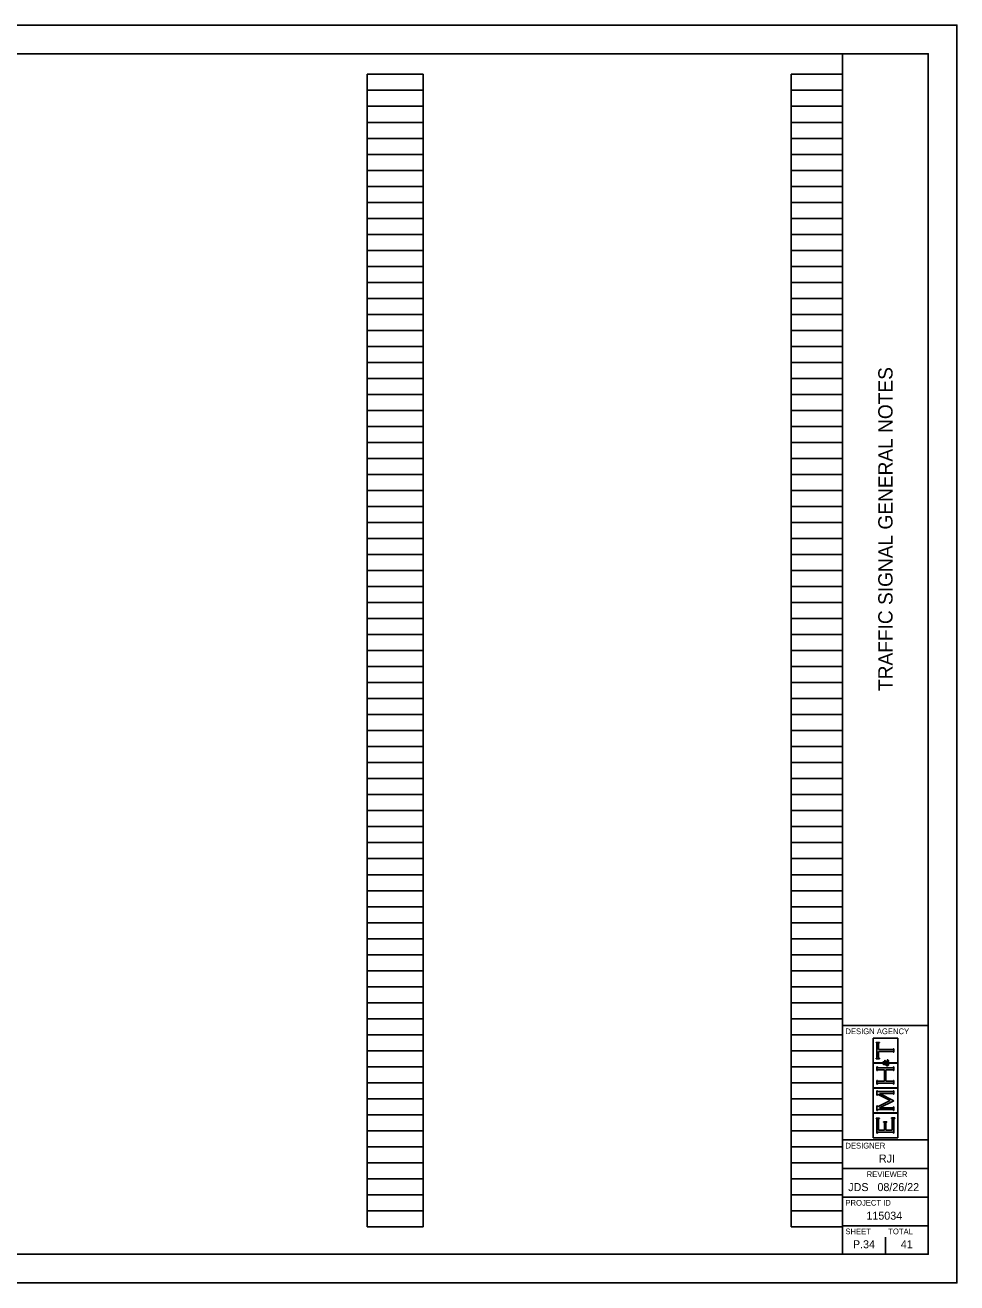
# Model space of a CAD drawing. Extents: x 0 to 34, y 0 to 22.
# Drawn here: x 17.7 to 34, y 0 to 22 of the extents above; entities that cross this region are included whole.
import ezdxf

# ---------------------------------------------------------------- set-up
doc = ezdxf.new("R2010")
doc.units = 0
for name, color, linetype in [('SH_Border', 7, 'Continuous'), ('SH_Cut_Line', 7, 'Continuous'), ('SH_Data', 7, 'Continuous')]:
    doc.layers.add(name, color=color, linetype=linetype)

msp = doc.modelspace()

# ---------------------------------------------------------------- linework, layer by layer
at = {"layer": 'SH_Border'}
for p, q in [((32, 0.5), (32, 21.5)), ((32, 4.5), (33.5, 4.5)), ((32, 2.5), (33.5, 2.5)), ((32, 2), (33.5, 2)), ((32, 1.5), (33.5, 1.5)), ((32, 1), (33.5, 1))]:
    msp.add_line(p, q, dxfattribs=at)
msp.add_lwpolyline([(1.5, 21.5), (33.5, 21.5), (33.5, 0.5), (1.5, 0.5)], close=True, dxfattribs=at)
at = {"layer": 'SH_Cut_Line'}
msp.add_lwpolyline([(0, 0), (34, 0), (34, 22), (0, 22)], close=True, dxfattribs=at)
at = {"layer": 'SH_Data'}
for p, q in [((23.68, 0.98), (23.68, 21.14)), ((23.68, 21.14), (24.66, 21.14)), ((24.66, 0.98), (24.66, 21.14)), ((31.1, 0.98), (31.1, 21.14)), ((31.1, 21.14), (32, 21.14)), ((32, 0.98), (32, 21.14)), ((23.68, 20.86), (24.66, 20.86)), ((31.1, 20.86), (32, 20.86)), ((23.68, 20.58), (24.66, 20.58)), ((31.1, 20.58), (32, 20.58)), ((23.68, 20.3), (24.66, 20.3)), ((31.1, 20.3), (32, 20.3)), ((23.68, 20.02), (24.66, 20.02)), ((31.1, 20.02), (32, 20.02)), ((23.68, 19.74), (24.66, 19.74)), ((31.1, 19.74), (32, 19.74)), ((23.68, 19.46), (24.66, 19.46)), ((31.1, 19.46), (32, 19.46)), ((23.68, 19.18), (24.66, 19.18)), ((31.1, 19.18), (32, 19.18)), ((23.68, 18.9), (24.66, 18.9)), ((31.1, 18.9), (32, 18.9)), ((23.68, 18.62), (24.66, 18.62)), ((31.1, 18.62), (32, 18.62)), ((23.68, 18.34), (24.66, 18.34)), ((31.1, 18.34), (32, 18.34)), ((23.68, 18.06), (24.66, 18.06)), ((31.1, 18.06), (32, 18.06)), ((23.68, 17.78), (24.66, 17.78)), ((31.1, 17.78), (32, 17.78)), ((23.68, 17.5), (24.66, 17.5)), ((31.1, 17.5), (32, 17.5)), ((23.68, 17.22), (24.66, 17.22)), ((31.1, 17.22), (32, 17.22)), ((23.68, 16.94), (24.66, 16.94)), ((31.1, 16.94), (32, 16.94)), ((23.68, 16.66), (24.66, 16.66)), ((31.1, 16.66), (32, 16.66)), ((23.68, 16.38), (24.66, 16.38)), ((31.1, 16.38), (32, 16.38)), ((23.68, 16.1), (24.66, 16.1)), ((31.1, 16.1), (32, 16.1)), ((23.68, 15.82), (24.66, 15.82)), ((31.1, 15.82), (32, 15.82)), ((23.68, 15.54), (24.66, 15.54)), ((31.1, 15.54), (32, 15.54)), ((23.68, 15.26), (24.66, 15.26)), ((31.1, 15.26), (32, 15.26)), ((23.68, 14.98), (24.66, 14.98)), ((31.1, 14.98), (32, 14.98)), ((23.68, 14.7), (24.66, 14.7)), ((31.1, 14.7), (32, 14.7)), ((23.68, 14.42), (24.66, 14.42)), ((31.1, 14.42), (32, 14.42)), ((23.68, 14.14), (24.66, 14.14)), ((31.1, 14.14), (32, 14.14)), ((23.68, 13.86), (24.66, 13.86)), ((31.1, 13.86), (32, 13.86)), ((23.68, 13.58), (24.66, 13.58)), ((31.1, 13.58), (32, 13.58)), ((23.68, 13.3), (24.66, 13.3)), ((31.1, 13.3), (32, 13.3)), ((23.68, 13.02), (24.66, 13.02)), ((31.1, 13.02), (32, 13.02)), ((23.68, 12.74), (24.66, 12.74)), ((31.1, 12.74), (32, 12.74)), ((23.68, 12.46), (24.66, 12.46)), ((31.1, 12.46), (32, 12.46)), ((23.68, 12.18), (24.66, 12.18)), ((31.1, 12.18), (32, 12.18)), ((23.68, 11.9), (24.66, 11.9)), ((31.1, 11.9), (32, 11.9)), ((23.68, 11.62), (24.66, 11.62)), ((31.1, 11.62), (32, 11.62)), ((23.68, 11.34), (24.66, 11.34)), ((31.1, 11.34), (32, 11.34)), ((23.68, 11.06), (24.66, 11.06)), ((31.1, 11.06), (32, 11.06)), ((23.68, 10.78), (24.66, 10.78)), ((31.1, 10.78), (32, 10.78)), ((23.68, 10.5), (24.66, 10.5)), ((31.1, 10.5), (32, 10.5)), ((23.68, 10.22), (24.66, 10.22)), ((31.1, 10.22), (32, 10.22)), ((23.68, 9.94), (24.66, 9.94)), ((31.1, 9.94), (32, 9.94)), ((23.68, 9.66), (24.66, 9.66)), ((31.1, 9.66), (32, 9.66)), ((23.68, 9.38), (24.66, 9.38)), ((31.1, 9.38), (32, 9.38)), ((23.68, 9.1), (24.66, 9.1)), ((31.1, 9.1), (32, 9.1)), ((23.68, 8.82), (24.66, 8.82)), ((31.1, 8.82), (32, 8.82)), ((23.68, 8.54), (24.66, 8.54)), ((31.1, 8.54), (32, 8.54)), ((23.68, 8.26), (24.66, 8.26)), ((31.1, 8.26), (32, 8.26)), ((23.68, 7.98), (24.66, 7.98)), ((31.1, 7.98), (32, 7.98)), ((23.68, 7.7), (24.66, 7.7)), ((31.1, 7.7), (32, 7.7)), ((23.68, 7.42), (24.66, 7.42)), ((31.1, 7.42), (32, 7.42)), ((23.68, 7.14), (24.66, 7.14)), ((31.1, 7.14), (32, 7.14)), ((23.68, 6.86), (24.66, 6.86)), ((31.1, 6.86), (32, 6.86)), ((23.68, 6.58), (24.66, 6.58)), ((31.1, 6.58), (32, 6.58)), ((23.68, 6.3), (24.66, 6.3)), ((31.1, 6.3), (32, 6.3)), ((23.68, 6.02), (24.66, 6.02)), ((31.1, 6.02), (32, 6.02)), ((23.68, 5.74), (24.66, 5.74)), ((31.1, 5.74), (32, 5.74)), ((23.68, 5.46), (24.66, 5.46)), ((31.1, 5.46), (32, 5.46)), ((23.68, 5.18), (24.66, 5.18)), ((31.1, 5.18), (32, 5.18)), ((23.68, 4.9), (24.66, 4.9)), ((31.1, 4.9), (32, 4.9)), ((23.68, 4.62), (24.66, 4.62)), ((31.1, 4.62), (32, 4.62)), ((23.68, 4.34), (24.66, 4.34)), ((31.1, 4.34), (32, 4.34)), ((32.966, 4.28), (32.534, 4.28)), ((32.534, 4.28), (32.534, 3.848)), ((32.588, 4.199), (32.588, 4.206)), ((32.588, 4.206), (32.644, 4.206)), ((32.594, 4.198), (32.588, 4.199)), ((32.598, 4.196), (32.594, 4.198)), ((32.599, 4.194), (32.598, 4.196)), ((32.601, 4.191), (32.599, 4.194)), ((32.602, 4.187), (32.601, 4.191)), ((32.602, 4.181), (32.602, 4.187)), ((32.602, 3.947), (32.602, 4.181)), ((32.632, 4.191), (32.631, 4.187)), ((32.631, 4.187), (32.631, 4.181)), ((32.631, 4.181), (32.631, 4.081)), ((32.633, 4.194), (32.632, 4.191)), ((32.635, 4.196), (32.633, 4.194)), ((32.639, 4.198), (32.635, 4.196)), ((32.644, 4.199), (32.639, 4.198)), ((32.644, 4.206), (32.644, 4.199)), ((32.966, 3.848), (32.966, 4.28)), ((23.68, 4.06), (24.66, 4.06)), ((31.1, 4.06), (32, 4.06)), ((32.631, 4.081), (32.872, 4.081)), ((32.872, 4.047), (32.631, 4.047)), ((32.631, 4.047), (32.631, 3.947)), ((32.872, 4.081), (32.878, 4.081)), ((32.878, 4.047), (32.872, 4.047)), ((32.878, 4.081), (32.882, 4.082)), ((32.883, 4.046), (32.878, 4.047)), ((32.882, 4.082), (32.885, 4.084)), ((32.885, 4.044), (32.883, 4.046)), ((32.885, 4.084), (32.887, 4.085)), ((32.888, 4.042), (32.885, 4.044)), ((32.887, 4.085), (32.889, 4.089)), ((32.889, 4.039), (32.888, 4.042)), ((32.889, 4.089), (32.891, 4.095)), ((32.891, 4.033), (32.889, 4.039)), ((32.891, 4.095), (32.898, 4.095)), ((32.898, 4.033), (32.891, 4.033)), ((32.898, 4.095), (32.898, 4.033)), ((23.68, 3.78), (24.66, 3.78)), ((31.1, 3.78), (32, 3.78)), ((32.534, 3.848), (32.693, 3.848)), ((32.693, 3.842), (32.534, 3.842)), ((32.534, 3.842), (32.534, 3.41)), ((32.588, 3.928), (32.594, 3.93)), ((32.588, 3.921), (32.588, 3.928)), ((32.644, 3.921), (32.588, 3.921)), ((32.594, 3.93), (32.598, 3.932)), ((32.598, 3.932), (32.599, 3.934)), ((32.599, 3.934), (32.601, 3.937)), ((32.601, 3.937), (32.602, 3.941)), ((32.602, 3.941), (32.602, 3.947)), ((32.602, 3.714), (32.602, 3.776)), ((32.602, 3.776), (32.609, 3.776)), ((32.609, 3.776), (32.611, 3.77)), ((32.611, 3.77), (32.612, 3.766)), ((32.612, 3.766), (32.615, 3.765)), ((32.615, 3.765), (32.617, 3.763)), ((32.617, 3.763), (32.622, 3.762)), ((32.622, 3.762), (32.628, 3.762)), ((32.628, 3.762), (32.872, 3.762)), ((32.631, 3.947), (32.631, 3.941)), ((32.631, 3.941), (32.632, 3.937)), ((32.632, 3.937), (32.633, 3.934)), ((32.633, 3.934), (32.635, 3.932)), ((32.635, 3.932), (32.639, 3.93)), ((32.639, 3.93), (32.644, 3.928)), ((32.644, 3.928), (32.644, 3.921)), ((32.693, 3.848), (32.693, 3.842)), ((32.701, 3.852), (32.703, 3.857)), ((32.701, 3.846), (32.701, 3.852)), ((32.701, 3.84), (32.701, 3.846)), ((32.703, 3.835), (32.701, 3.84)), ((32.703, 3.857), (32.706, 3.861)), ((32.706, 3.83), (32.703, 3.835)), ((32.706, 3.861), (32.71, 3.864)), ((32.707, 3.852), (32.706, 3.849)), ((32.706, 3.849), (32.706, 3.846)), ((32.706, 3.846), (32.706, 3.842)), ((32.706, 3.842), (32.708, 3.839)), ((32.71, 3.824), (32.706, 3.83)), ((32.71, 3.854), (32.707, 3.852)), ((32.708, 3.839), (32.711, 3.837)), ((32.71, 3.864), (32.714, 3.866)), ((32.712, 3.856), (32.71, 3.854)), ((32.717, 3.821), (32.71, 3.824)), ((32.711, 3.837), (32.714, 3.835)), ((32.715, 3.857), (32.712, 3.856)), ((32.714, 3.866), (32.719, 3.866)), ((32.714, 3.835), (32.716, 3.834)), ((32.718, 3.857), (32.715, 3.857)), ((32.716, 3.834), (32.719, 3.834)), ((32.725, 3.821), (32.717, 3.821)), ((32.723, 3.857), (32.718, 3.857)), ((32.719, 3.866), (32.724, 3.866)), ((32.719, 3.834), (32.722, 3.834)), ((32.722, 3.834), (32.724, 3.834)), ((32.727, 3.856), (32.723, 3.857)), ((32.724, 3.866), (32.728, 3.864)), ((32.724, 3.834), (32.727, 3.835)), ((32.728, 3.821), (32.725, 3.821)), ((32.73, 3.853), (32.727, 3.856)), ((32.727, 3.835), (32.73, 3.836)), ((32.728, 3.864), (32.732, 3.861)), ((32.731, 3.822), (32.728, 3.821)), ((32.734, 3.85), (32.73, 3.853)), ((32.73, 3.836), (32.734, 3.837)), ((32.734, 3.822), (32.731, 3.822)), ((32.732, 3.861), (32.736, 3.857)), ((32.737, 3.845), (32.734, 3.85)), ((32.734, 3.837), (32.74, 3.839)), ((32.737, 3.823), (32.734, 3.822)), ((32.736, 3.857), (32.74, 3.851)), ((32.74, 3.839), (32.737, 3.845)), ((32.741, 3.825), (32.737, 3.823)), ((32.738, 3.867), (32.738, 3.898)), ((32.738, 3.898), (32.741, 3.898)), ((32.741, 3.867), (32.738, 3.867)), ((32.74, 3.851), (32.745, 3.842)), ((32.741, 3.898), (32.741, 3.894)), ((32.741, 3.894), (32.742, 3.891)), ((32.742, 3.871), (32.741, 3.869)), ((32.741, 3.869), (32.741, 3.867)), ((32.746, 3.827), (32.741, 3.825)), ((32.742, 3.891), (32.744, 3.889)), ((32.743, 3.872), (32.742, 3.871)), ((32.745, 3.873), (32.743, 3.872)), ((32.744, 3.889), (32.745, 3.887)), ((32.745, 3.887), (32.75, 3.883)), ((32.747, 3.874), (32.745, 3.873)), ((32.745, 3.842), (32.755, 3.848)), ((32.753, 3.815), (32.746, 3.827)), ((32.749, 3.874), (32.747, 3.874)), ((32.756, 3.874), (32.749, 3.874)), ((32.75, 3.883), (32.757, 3.879)), ((32.757, 3.832), (32.751, 3.829)), ((32.751, 3.829), (32.755, 3.824)), ((32.759, 3.808), (32.753, 3.815)), ((32.755, 3.848), (32.765, 3.855)), ((32.755, 3.824), (32.758, 3.819)), ((32.764, 3.87), (32.756, 3.874)), ((32.757, 3.879), (32.765, 3.875)), ((32.762, 3.835), (32.757, 3.832)), ((32.758, 3.819), (32.762, 3.817)), ((32.765, 3.803), (32.759, 3.808)), ((32.766, 3.838), (32.762, 3.835)), ((32.762, 3.817), (32.766, 3.814)), ((32.775, 3.861), (32.764, 3.87)), ((32.765, 3.875), (32.772, 3.87)), ((32.765, 3.855), (32.775, 3.861)), ((32.77, 3.799), (32.765, 3.803)), ((32.77, 3.84), (32.766, 3.838)), ((32.766, 3.814), (32.771, 3.812)), ((32.776, 3.845), (32.77, 3.84)), ((32.776, 3.797), (32.77, 3.799)), ((32.771, 3.812), (32.775, 3.812)), ((32.772, 3.87), (32.779, 3.865)), ((32.775, 3.812), (32.78, 3.812)), ((32.785, 3.851), (32.776, 3.845)), ((32.782, 3.797), (32.776, 3.797)), ((32.779, 3.865), (32.784, 3.869)), ((32.78, 3.812), (32.785, 3.814)), ((32.781, 3.9), (32.783, 3.902)), ((32.785, 3.899), (32.781, 3.9)), ((32.788, 3.797), (32.782, 3.797)), ((32.783, 3.902), (32.79, 3.901)), ((32.784, 3.869), (32.787, 3.873)), ((32.788, 3.897), (32.785, 3.899)), ((32.789, 3.846), (32.785, 3.851)), ((32.785, 3.814), (32.789, 3.817)), ((32.787, 3.873), (32.789, 3.876)), ((32.789, 3.895), (32.788, 3.897)), ((32.793, 3.8), (32.788, 3.797)), ((32.791, 3.892), (32.789, 3.895)), ((32.789, 3.876), (32.791, 3.88)), ((32.794, 3.859), (32.789, 3.855)), ((32.789, 3.855), (32.795, 3.849)), ((32.792, 3.842), (32.789, 3.846)), ((32.789, 3.817), (32.793, 3.821)), ((32.79, 3.901), (32.795, 3.898)), ((32.792, 3.89), (32.791, 3.892)), ((32.791, 3.88), (32.792, 3.883)), ((32.792, 3.886), (32.792, 3.89)), ((32.792, 3.883), (32.792, 3.886)), ((32.793, 3.839), (32.792, 3.842)), ((32.794, 3.837), (32.793, 3.839)), ((32.793, 3.821), (32.795, 3.825)), ((32.797, 3.804), (32.793, 3.8)), ((32.798, 3.864), (32.794, 3.859)), ((32.795, 3.834), (32.794, 3.837)), ((32.795, 3.898), (32.799, 3.894)), ((32.795, 3.849), (32.798, 3.843)), ((32.795, 3.831), (32.795, 3.834)), ((32.795, 3.825), (32.795, 3.831)), ((32.801, 3.809), (32.797, 3.804)), ((32.8, 3.868), (32.798, 3.864)), ((32.798, 3.843), (32.8, 3.839)), ((32.799, 3.894), (32.802, 3.89)), ((32.802, 3.872), (32.8, 3.868)), ((32.8, 3.839), (32.802, 3.834)), ((32.803, 3.815), (32.801, 3.809)), ((32.802, 3.89), (32.803, 3.885)), ((32.803, 3.876), (32.802, 3.872)), ((32.802, 3.834), (32.803, 3.829)), ((32.803, 3.885), (32.803, 3.88)), ((32.803, 3.88), (32.803, 3.876)), ((32.807, 3.842), (32.803, 3.848)), ((32.803, 3.848), (32.966, 3.848)), ((32.803, 3.829), (32.803, 3.823)), ((32.803, 3.823), (32.803, 3.815)), ((32.966, 3.842), (32.807, 3.842)), ((32.872, 3.762), (32.878, 3.762)), ((32.878, 3.762), (32.882, 3.763)), ((32.882, 3.763), (32.885, 3.765)), ((32.885, 3.765), (32.887, 3.766)), ((32.887, 3.766), (32.889, 3.77)), ((32.889, 3.77), (32.891, 3.776)), ((32.891, 3.776), (32.898, 3.776)), ((32.898, 3.776), (32.898, 3.714)), ((32.966, 3.41), (32.966, 3.842)), ((32.609, 3.714), (32.602, 3.714)), ((32.602, 3.477), (32.602, 3.538)), ((32.602, 3.538), (32.609, 3.538)), ((32.61, 3.72), (32.609, 3.714)), ((32.609, 3.538), (32.611, 3.533)), ((32.612, 3.723), (32.61, 3.72)), ((32.611, 3.533), (32.612, 3.529)), ((32.615, 3.725), (32.612, 3.723)), ((32.612, 3.529), (32.615, 3.527)), ((32.617, 3.727), (32.615, 3.725)), ((32.615, 3.527), (32.617, 3.526)), ((32.622, 3.728), (32.617, 3.727)), ((32.617, 3.526), (32.622, 3.525)), ((32.628, 3.728), (32.622, 3.728)), ((32.622, 3.525), (32.628, 3.525)), ((32.732, 3.728), (32.628, 3.728)), ((32.628, 3.525), (32.732, 3.525)), ((32.732, 3.525), (32.732, 3.728)), ((32.872, 3.728), (32.76, 3.728)), ((32.76, 3.728), (32.76, 3.525)), ((32.76, 3.525), (32.872, 3.525)), ((32.878, 3.728), (32.872, 3.728)), ((32.872, 3.525), (32.878, 3.525)), ((32.883, 3.727), (32.878, 3.728)), ((32.878, 3.525), (32.883, 3.525)), ((32.885, 3.725), (32.883, 3.727)), ((32.883, 3.525), (32.885, 3.527)), ((32.888, 3.723), (32.885, 3.725)), ((32.885, 3.527), (32.888, 3.529)), ((32.889, 3.72), (32.888, 3.723)), ((32.888, 3.529), (32.889, 3.533)), ((32.891, 3.714), (32.889, 3.72)), ((32.889, 3.533), (32.891, 3.538)), ((32.898, 3.714), (32.891, 3.714)), ((32.891, 3.538), (32.898, 3.538)), ((32.898, 3.538), (32.898, 3.477)), ((23.68, 3.5), (24.66, 3.5)), ((31.1, 3.5), (32, 3.5)), ((32.534, 3.41), (32.966, 3.41)), ((32.966, 3.405), (32.534, 3.405)), ((32.534, 3.405), (32.534, 2.973)), ((32.609, 3.477), (32.602, 3.477)), ((32.602, 3.283), (32.602, 3.36)), ((32.602, 3.36), (32.609, 3.36)), ((32.61, 3.482), (32.609, 3.477)), ((32.609, 3.36), (32.611, 3.354)), ((32.612, 3.486), (32.61, 3.482)), ((32.611, 3.354), (32.612, 3.351)), ((32.615, 3.488), (32.612, 3.486)), ((32.612, 3.351), (32.615, 3.349)), ((32.617, 3.49), (32.615, 3.488)), ((32.615, 3.349), (32.617, 3.347)), ((32.622, 3.491), (32.617, 3.49)), ((32.617, 3.347), (32.622, 3.346)), ((32.628, 3.491), (32.622, 3.491)), ((32.622, 3.346), (32.628, 3.346)), ((32.872, 3.491), (32.628, 3.491)), ((32.628, 3.346), (32.872, 3.346)), ((32.872, 3.312), (32.649, 3.312)), ((32.649, 3.312), (32.898, 3.186)), ((32.75, 3.5), (32.75, 3.5)), ((32.878, 3.491), (32.872, 3.491)), ((32.872, 3.346), (32.878, 3.346)), ((32.878, 3.312), (32.872, 3.312)), ((32.883, 3.49), (32.878, 3.491)), ((32.878, 3.346), (32.882, 3.347)), ((32.883, 3.311), (32.878, 3.312)), ((32.882, 3.347), (32.885, 3.349)), ((32.885, 3.488), (32.883, 3.49)), ((32.885, 3.31), (32.883, 3.311)), ((32.887, 3.486), (32.885, 3.488)), ((32.885, 3.349), (32.887, 3.351)), ((32.887, 3.308), (32.885, 3.31)), ((32.887, 3.351), (32.889, 3.354)), ((32.889, 3.304), (32.887, 3.308)), ((32.889, 3.482), (32.887, 3.486)), ((32.891, 3.477), (32.889, 3.482)), ((32.889, 3.354), (32.891, 3.36)), ((32.891, 3.298), (32.889, 3.304)), ((32.898, 3.477), (32.891, 3.477)), ((32.891, 3.36), (32.898, 3.36)), ((32.898, 3.36), (32.898, 3.298)), ((32.966, 2.973), (32.966, 3.405)), ((23.68, 3.22), (24.66, 3.22)), ((31.1, 3.22), (32, 3.22)), ((32.609, 3.283), (32.602, 3.283)), ((32.602, 3.017), (32.602, 3.094)), ((32.602, 3.094), (32.609, 3.094)), ((32.612, 3.29), (32.609, 3.283)), ((32.609, 3.094), (32.612, 3.087)), ((32.615, 3.293), (32.612, 3.29)), ((32.612, 3.087), (32.615, 3.083)), ((32.618, 3.293), (32.615, 3.293)), ((32.615, 3.083), (32.618, 3.083)), ((32.621, 3.293), (32.618, 3.293)), ((32.618, 3.083), (32.62, 3.083)), ((32.62, 3.083), (32.625, 3.086)), ((32.626, 3.292), (32.621, 3.293)), ((32.625, 3.086), (32.635, 3.09)), ((32.633, 3.288), (32.626, 3.292)), ((32.831, 3.189), (32.633, 3.288)), ((32.635, 3.09), (32.831, 3.189)), ((32.898, 3.186), (32.649, 3.062)), ((32.898, 3.298), (32.891, 3.298)), ((23.68, 2.94), (24.66, 2.94)), ((31.1, 2.94), (32, 2.94)), ((32.534, 2.973), (32.966, 2.973)), ((32.966, 2.967), (32.534, 2.967)), ((32.534, 2.967), (32.534, 2.535)), ((32.588, 2.874), (32.588, 2.881)), ((32.588, 2.881), (32.644, 2.881)), ((32.594, 2.873), (32.588, 2.874)), ((32.598, 2.871), (32.594, 2.873)), ((32.599, 2.868), (32.598, 2.871)), ((32.601, 2.866), (32.599, 2.868)), ((32.602, 2.862), (32.601, 2.866)), ((32.609, 3.017), (32.602, 3.017)), ((32.602, 2.856), (32.602, 2.862)), ((32.61, 3.023), (32.609, 3.017)), ((32.612, 3.026), (32.61, 3.023)), ((32.615, 3.028), (32.612, 3.026)), ((32.617, 3.03), (32.615, 3.028)), ((32.622, 3.031), (32.617, 3.03)), ((32.628, 3.031), (32.622, 3.031)), ((32.872, 3.031), (32.628, 3.031)), ((32.632, 2.866), (32.631, 2.862)), ((32.631, 2.862), (32.631, 2.856)), ((32.633, 2.868), (32.632, 2.866)), ((32.635, 2.871), (32.633, 2.868)), ((32.639, 2.873), (32.635, 2.871)), ((32.644, 2.874), (32.639, 2.873)), ((32.644, 2.881), (32.644, 2.874)), ((32.649, 3.062), (32.872, 3.062)), ((32.855, 2.877), (32.855, 2.884)), ((32.855, 2.884), (32.912, 2.884)), ((32.861, 2.876), (32.855, 2.877)), ((32.865, 2.874), (32.861, 2.876)), ((32.867, 2.872), (32.865, 2.874)), ((32.868, 2.869), (32.867, 2.872)), ((32.869, 2.865), (32.868, 2.869)), ((32.869, 2.859), (32.869, 2.865)), ((32.872, 3.062), (32.878, 3.062)), ((32.878, 3.031), (32.872, 3.031)), ((32.878, 3.062), (32.882, 3.063)), ((32.883, 3.03), (32.878, 3.031)), ((32.882, 3.063), (32.885, 3.065)), ((32.885, 3.028), (32.883, 3.03)), ((32.885, 3.065), (32.887, 3.067)), ((32.887, 3.026), (32.885, 3.028)), ((32.887, 3.067), (32.889, 3.07)), ((32.889, 3.023), (32.887, 3.026)), ((32.889, 3.07), (32.891, 3.076)), ((32.891, 3.017), (32.889, 3.023)), ((32.891, 3.076), (32.898, 3.076)), ((32.898, 3.017), (32.891, 3.017)), ((32.898, 3.076), (32.898, 3.017)), ((32.899, 2.869), (32.898, 2.865)), ((32.898, 2.865), (32.898, 2.858)), ((32.901, 2.871), (32.899, 2.869)), ((32.903, 2.874), (32.901, 2.871)), ((32.906, 2.876), (32.903, 2.874)), ((32.912, 2.877), (32.906, 2.876)), ((32.912, 2.884), (32.912, 2.877)), ((32.966, 2.535), (32.966, 2.967)), ((23.68, 2.66), (24.66, 2.66)), ((31.1, 2.66), (32, 2.66)), ((32.602, 2.621), (32.602, 2.856)), ((32.631, 2.856), (32.631, 2.669)), ((32.631, 2.669), (32.732, 2.669)), ((32.718, 2.81), (32.718, 2.816)), ((32.718, 2.816), (32.774, 2.816)), ((32.723, 2.808), (32.718, 2.81)), ((32.727, 2.806), (32.723, 2.808)), ((32.729, 2.804), (32.727, 2.806)), ((32.731, 2.801), (32.729, 2.804)), ((32.732, 2.797), (32.731, 2.801)), ((32.732, 2.791), (32.732, 2.797)), ((32.732, 2.669), (32.732, 2.791)), ((32.761, 2.801), (32.76, 2.797)), ((32.76, 2.797), (32.76, 2.791)), ((32.76, 2.791), (32.76, 2.669)), ((32.76, 2.669), (32.869, 2.669)), ((32.763, 2.804), (32.761, 2.801)), ((32.765, 2.806), (32.763, 2.804)), ((32.768, 2.808), (32.765, 2.806)), ((32.774, 2.81), (32.768, 2.808)), ((32.774, 2.816), (32.774, 2.81)), ((32.869, 2.669), (32.869, 2.859)), ((32.898, 2.858), (32.898, 2.621)), ((32.534, 2.535), (32.966, 2.535)), ((32.609, 2.621), (32.602, 2.621)), ((32.611, 2.626), (32.609, 2.621)), ((32.612, 2.63), (32.611, 2.626)), ((32.615, 2.632), (32.612, 2.63)), ((32.617, 2.634), (32.615, 2.632)), ((32.622, 2.635), (32.617, 2.634)), ((32.628, 2.635), (32.622, 2.635)), ((32.872, 2.635), (32.628, 2.635)), ((32.878, 2.635), (32.872, 2.635)), ((32.883, 2.634), (32.878, 2.635)), ((32.885, 2.632), (32.883, 2.634)), ((32.887, 2.63), (32.885, 2.632)), ((32.889, 2.627), (32.887, 2.63)), ((32.891, 2.621), (32.889, 2.627)), ((32.898, 2.621), (32.891, 2.621)), ((23.68, 2.38), (24.66, 2.38)), ((31.1, 2.38), (32, 2.38)), ((23.68, 2.1), (24.66, 2.1)), ((31.1, 2.1), (32, 2.1)), ((23.68, 1.82), (24.66, 1.82)), ((31.1, 1.82), (32, 1.82)), ((23.68, 1.54), (24.66, 1.54)), ((31.1, 1.54), (32, 1.54)), ((23.68, 1.26), (24.66, 1.26)), ((31.1, 1.26), (32, 1.26)), ((23.68, 0.98), (24.66, 0.98)), ((31.1, 0.98), (32, 0.98)), ((32.375, 0.675), (32.375, 0.675)), ((32.75, 0.5), (32.75, 0.8))]:
    msp.add_line(p, q, dxfattribs=at)

# ---------------------------------------------------------------- texts
msp.add_text('TRAFFIC SIGNAL GENERAL NOTES', height=0.25, rotation=90, dxfattribs=at).set_placement((32.875, 10.353))
for s, height, p in [('DESIGN AGENCY', 0.1, (32.05, 4.35)), ('DESIGNER', 0.1, (32.05, 2.35)), ('RJI', 0.14, (32.636, 2.105)), ('REVIEWER', 0.1, (32.422, 1.85)), ('JDS', 0.14, (32.1, 1.605)), ('08/26/22', 0.14, (32.611, 1.605)), ('PROJECT ID', 0.1, (32.05, 1.35)), ('115034', 0.14, (32.418, 1.105)), ('SHEET', 0.1, (32.05, 0.85)), ('TOTAL', 0.1, (32.8, 0.85)), ('P.34', 0.14, (32.182, 0.605)), ('41', 0.14, (33.019, 0.605))]:
    msp.add_text(s, height=height, dxfattribs=at).set_placement(p)

doc.saveas('drawing.dxf')
